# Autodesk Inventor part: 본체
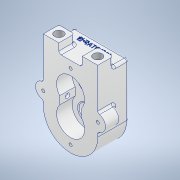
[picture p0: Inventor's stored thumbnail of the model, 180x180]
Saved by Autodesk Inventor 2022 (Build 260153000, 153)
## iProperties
Created: 2024-03
Part Number: 본체
Material: 알루미늄 6061
Document SubType Name: Modeling
Designer: PC-12
Density: 2.7 g/cm^3
Appearance: 알루미늄 - 평지
Author: PC-12
## Parameters: d0 = 35 mm, d2 = 33 mm, d4 = 0, d7 = 12 mm, d8 = 0, d11 = 63.5 mm, d13 = 0, d14 = 52 mm, d15 = 6 mm, d16 = 0, d17 = 32 mm, d18 = 4 mm, d19 = 0, d21 = 36 mm, d22 = 36 mm, d23 = 33 mm, d24 = 28 mm, d25 = 14 mm, d27 = 0, d31 = 0, d32 = 15 mm, d33 = 0, d34 = 0, d35 = 25 mm, d36 = 7.3 mm, d37 = 0, d38 = 14 mm, d39 = 7.3 mm, d40 = -60 deg, d41 = 3 mm, d42 = 1 mm, d43 = 2 mm, d44 = 45 deg, d45 = -0.7 mm, d46 = 7.3 mm, d47 = 30 deg, d48 = 6 mm, d49 = 6 mm, d51 = 25 mm, d54 = 63.5 mm, d55 = 63.5 mm, d56 = 8 mm, d57 = 0, d58 = 0, d59 = 4.134 mm, d61 = 4 mm, d62 = 2 mm, d63 = 90 deg, d64 = 12 mm, d65 = 0, d66 = 26 mm, d67 = 59 mm, d68 = 42 mm, d69 = 3.242 mm, d70 = 8 mm, d71 = 4 mm, d72 = 2 mm, d73 = 90 deg, d75 = 0, d76 = 11.445 mm, d77 = 13 mm, d78 = 4 mm, d79 = 2 mm, d80 = 90 deg, d81 = 16 mm, d82 = 118 deg, d83 = 1 mm, d84 = 2 mm, d85 = 45 deg, d87 = 0.5 mm, d88 = 0
